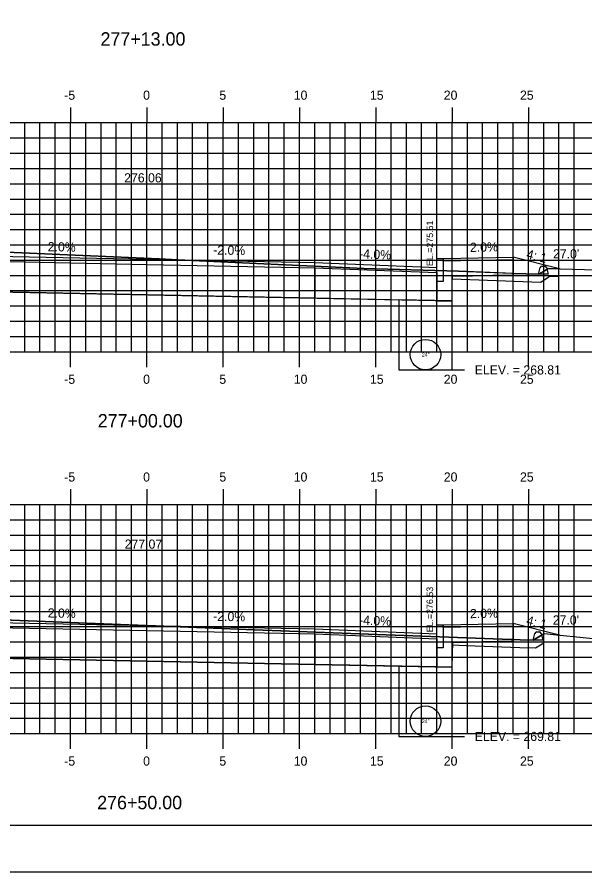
# Model space of a CAD drawing. Extents: x 854008 to 854178, y 366268 to 366378.
# Drawn here: x 854082.6 to 854119.8, y 366268.2 to 366324.1 of the extents above; entities that cross this region are included whole.
import ezdxf

# ---------------------------------------------------------------- set-up
doc = ezdxf.new("R2010")
doc.units = 0
for name, color, linetype in [('ANNOTATION', 7, 'Continuous'), ('BORDER', 7, 'Continuous'), ('D_Curb_Type_1_Rt', 7, 'Continuous'), ('D_Roadway_Centerline_Text', 7, 'Continuous'), ('D_Roadway_Edge_TW', 7, 'Continuous'), ('D_Roadway_FinishedGrade', 7, 'Continuous'), ('D_Roadway_Sidewalks_Paved', 7, 'Continuous'), ('D_Roadway_SubGrade', 7, 'Continuous'), ('D_Text_Standard', 7, 'Continuous'), ('H_V ANNOTATION', 7, 'Continuous'), ('JUNK COM EXC', 7, 'Continuous'), ('JUNK FILL', 7, 'Continuous'), ('junk grubnfill', 7, 'Continuous'), ('junk strct exc', 7, 'Continuous'), ('MAJOR', 7, 'Continuous'), ('MINOR', 7, 'Continuous'), ('PDRAIN', 7, 'Continuous'), ('PLOT BOUNDARY', 7, 'Continuous'), ('S_Curb_Type_3', 7, 'Continuous'), ('S_Roadway_Centerline', 7, 'Continuous')]:
    doc.layers.add(name, color=color, linetype=linetype)

msp = doc.modelspace()

# ---------------------------------------------------------------- linework, layer by layer
at = {"layer": 'BORDER'}
msp.add_line((854016.103, 366271.236), (854176.103, 366271.236), dxfattribs=at)
at = {"layer": 'D_Curb_Type_1_Rt'}
for points in [[(854110.52, 366308.335), (854110.52, 366306.835), (854110.103, 366306.835), (854110.103, 366308.335)], [(854110.52, 366284.352), (854110.52, 366282.852), (854110.103, 366282.852), (854110.103, 366284.352)]]:
    msp.add_lwpolyline(points, close=True, dxfattribs=at)
at = {"layer": 'D_Roadway_Edge_TW'}
for points in [[(854072.103, 366308.192), (854080.103, 366308.512), (854102.103, 366308.072), (854110.099, 366307.751)], [(854072.103, 366308.192), (854080.103, 366308.512), (854102.103, 366308.072), (854110.099, 366307.751)], [(854072.103, 366284.209), (854080.103, 366284.529), (854102.103, 366284.089), (854110.099, 366283.769)]]:
    msp.add_lwpolyline(points, dxfattribs=at)
at = {"layer": 'D_Roadway_FinishedGrade'}
for p, q in [((854118.135, 366307.67), (854115.108, 366308.426)), ((854118.135, 366283.688), (854115.108, 366284.444))]:
    msp.add_line(p, q, dxfattribs=at)
at = {"layer": 'D_Roadway_Sidewalks_Paved'}
for points in [[(854110.519, 366308.335), (854115.108, 366308.426), (854115.108, 366308.26), (854110.519, 366308.168)], [(854110.519, 366284.352), (854115.108, 366284.444), (854115.108, 366284.277), (854110.519, 366284.185)]]:
    msp.add_lwpolyline(points, close=True, dxfattribs=at)
at = {"layer": 'D_Roadway_SubGrade'}
for p, q in [((854118.103, 366307.167), (854118.103, 366307.667)), ((854117.103, 366283.18), (854117.103, 366283.77))]:
    msp.add_line(p, q, dxfattribs=at)
for points in [[(854080.103, 366306.178), (854080.103, 366308.178), (854091.103, 366307.958), (854102.103, 366307.738), (854102.103, 366305.738), (854091.103, 366305.958)], [(854102.103, 366307.738), (854110.103, 366307.418), (854110.103, 366305.578), (854102.103, 366305.738)], [(854080.103, 366282.195), (854080.103, 366284.195), (854091.103, 366283.975), (854102.103, 366283.755), (854102.103, 366281.755), (854091.103, 366281.975)], [(854102.103, 366283.755), (854110.103, 366283.435), (854110.103, 366281.595), (854102.103, 366281.755)]]:
    msp.add_lwpolyline(points, close=True, dxfattribs=at)
for points in [[(854110.106, 366305.579), (854111.106, 366305.559), (854111.106, 366307.181), (854115.108, 366307.26), (854115.108, 366308.26)], [(854111.106, 366307.019), (854116.906, 366306.801), (854117.404, 366307.112), (854117.525, 366307.182), (854118.103, 366307.167)], [(854110.106, 366281.596), (854111.106, 366281.576), (854111.106, 366283.198), (854115.108, 366283.277), (854115.108, 366284.277)], [(854111.106, 366283.037), (854112.026, 366283.002), (854114.951, 366282.895), (854115.537, 366282.874), (854116.558, 366282.839), (854117.103, 366283.18)]]:
    msp.add_lwpolyline(points, dxfattribs=at)
at = {"layer": 'D_Text_Standard'}
for points in [[(854110.987, 366301.046), (854111.226, 366301.046), (854111.906, 366301.046)], [(854110.987, 366277.046), (854111.226, 366277.046), (854111.906, 366277.046)]]:
    msp.add_lwpolyline(points, dxfattribs=at)
at = {"layer": 'JUNK COM EXC'}
for points in [[(854115.108, 366307.369), (854111.511, 366307.504), (854105.338, 366307.696), (854093.132, 366308.264), (854091.919, 366308.317), (854082.419, 366308.728), (854081.643, 366308.761), (854073.044, 366308.446), (854067.098, 366308.296), (854067.098, 366307.7), (854071.103, 366307.62), (854071.103, 366305.998), (854080.103, 366306.178), (854111.106, 366305.559), (854111.106, 366307.181), (854115.108, 366307.26), (854115.108, 366307.369)], [(854067.098, 366284.408), (854067.098, 366283.717), (854071.103, 366283.637), (854071.103, 366282.015), (854080.103, 366282.195), (854102.103, 366281.755), (854111.106, 366281.576), (854111.139, 366283.231), (854115.108, 366283.277), (854115.108, 366283.389), (854114.969, 366283.394), (854112.044, 366283.502), (854105.033, 366283.764), (854098.156, 366284.024), (854091.667, 366284.28), (854089.919, 366284.352), (854081.695, 366284.68), (854074.422, 366284.545), (854067.098, 366284.408)]]:
    msp.add_lwpolyline(points, dxfattribs=at)
at = {"layer": 'JUNK FILL'}
for points in [[(854115.103, 366307.37), (854116.772, 366307.307), (854117.147, 366307.541), (854117.398, 366307.685), (854118.135, 366307.67), (854115.108, 366308.426), (854115.103, 366308.426)], [(854115.103, 366284.444), (854115.103, 366283.39), (854115.555, 366283.373), (854116.422, 366283.344), (854117.147, 366283.798), (854118.135, 366283.688), (854115.108, 366284.444)]]:
    msp.add_lwpolyline(points, close=True, dxfattribs=at)
at = {"layer": 'junk grubnfill'}
for points in [[(854118.103, 366307.167), (854118.103, 366307.667), (854117.398, 366307.685), (854117.147, 366307.541), (854116.772, 366307.307), (854115.108, 366307.369), (854115.108, 366307.26), (854111.106, 366307.181), (854111.106, 366307.019), (854116.906, 366306.801), (854117.404, 366307.112), (854117.525, 366307.182), (854118.103, 366307.167)], [(854117.103, 366283.18), (854117.103, 366283.77), (854116.422, 366283.344), (854115.555, 366283.373), (854115.108, 366283.389), (854115.108, 366283.277), (854111.106, 366283.198), (854111.106, 366283.037), (854112.026, 366283.002), (854114.951, 366282.895), (854115.537, 366282.874), (854116.558, 366282.839), (854117.103, 366283.18)]]:
    msp.add_lwpolyline(points, dxfattribs=at)
at = {"layer": 'junk strct exc'}
for points in [[(854107.606, 366305.628), (854107.606, 366301.046), (854111.106, 366301.046), (854111.106, 366305.559)], [(854107.606, 366281.645), (854107.606, 366277.046), (854111.106, 366277.046), (854111.106, 366281.576)]]:
    msp.add_lwpolyline(points, close=True, dxfattribs=at)
at = {"layer": 'MAJOR'}
for p, q in [((854086.103, 366318.238), (854086.103, 366317.236)), ((854091.103, 366318.238), (854091.103, 366317.236)), ((854096.103, 366318.238), (854096.103, 366317.236)), ((854101.103, 366318.238), (854101.103, 366317.236)), ((854106.103, 366318.238), (854106.103, 366317.236)), ((854111.103, 366318.238), (854111.103, 366317.236)), ((854116.103, 366318.238), (854116.103, 366317.236)), ((854021.103, 366317.236), (854161.103, 366317.236)), ((854021.103, 366317.236), (854161.103, 366317.236)), ((854086.103, 366302.236), (854086.103, 366317.236)), ((854091.103, 366302.236), (854091.103, 366317.236)), ((854096.103, 366302.236), (854096.103, 366317.236)), ((854101.103, 366302.236), (854101.103, 366317.236)), ((854106.103, 366302.236), (854106.103, 366317.236)), ((854111.103, 366302.236), (854111.103, 366317.236)), ((854116.103, 366302.236), (854116.103, 366317.236)), ((854021.103, 366312.236), (854161.103, 366312.236)), ((854021.103, 366307.236), (854161.103, 366307.236)), ((854021.103, 366302.236), (854161.103, 366302.236)), ((854021.103, 366302.236), (854161.103, 366302.236)), ((854086.103, 366301.234), (854086.103, 366302.236)), ((854091.103, 366301.234), (854091.103, 366302.236)), ((854096.103, 366301.234), (854096.103, 366302.236)), ((854101.103, 366301.234), (854101.103, 366302.236)), ((854106.103, 366301.234), (854106.103, 366302.236)), ((854111.103, 366301.234), (854111.103, 366302.236)), ((854116.103, 366301.234), (854116.103, 366302.236)), ((854086.103, 366293.238), (854086.103, 366292.236)), ((854091.103, 366293.238), (854091.103, 366292.236)), ((854096.103, 366293.238), (854096.103, 366292.236)), ((854101.103, 366293.238), (854101.103, 366292.236)), ((854106.103, 366293.238), (854106.103, 366292.236)), ((854111.103, 366293.238), (854111.103, 366292.236)), ((854116.103, 366293.238), (854116.103, 366292.236)), ((854021.103, 366292.236), (854161.103, 366292.236)), ((854021.103, 366292.236), (854161.103, 366292.236)), ((854086.103, 366277.236), (854086.103, 366292.236)), ((854091.103, 366277.236), (854091.103, 366292.236)), ((854096.103, 366277.236), (854096.103, 366292.236)), ((854101.103, 366277.236), (854101.103, 366292.236)), ((854106.103, 366277.236), (854106.103, 366292.236)), ((854111.103, 366277.236), (854111.103, 366292.236)), ((854116.103, 366277.236), (854116.103, 366292.236)), ((854021.103, 366287.236), (854161.103, 366287.236)), ((854021.103, 366282.236), (854161.103, 366282.236)), ((854021.103, 366277.236), (854161.103, 366277.236)), ((854021.103, 366277.236), (854161.103, 366277.236)), ((854086.103, 366276.234), (854086.103, 366277.236)), ((854091.103, 366276.234), (854091.103, 366277.236)), ((854096.103, 366276.234), (854096.103, 366277.236)), ((854101.103, 366276.234), (854101.103, 366277.236)), ((854106.103, 366276.234), (854106.103, 366277.236)), ((854111.103, 366276.234), (854111.103, 366277.236)), ((854116.103, 366276.234), (854116.103, 366277.236))]:
    msp.add_line(p, q, dxfattribs=at)
at = {"layer": 'MINOR'}
for p, q in [((854083.103, 366302.236), (854083.103, 366317.236)), ((854084.103, 366302.236), (854084.103, 366317.236)), ((854085.103, 366302.236), (854085.103, 366317.236)), ((854087.103, 366302.236), (854087.103, 366317.236)), ((854088.103, 366302.236), (854088.103, 366317.236)), ((854089.103, 366302.236), (854089.103, 366317.236)), ((854090.103, 366302.236), (854090.103, 366317.236)), ((854092.103, 366302.236), (854092.103, 366317.236)), ((854093.103, 366302.236), (854093.103, 366317.236)), ((854094.103, 366302.236), (854094.103, 366317.236)), ((854095.103, 366302.236), (854095.103, 366317.236)), ((854097.103, 366302.236), (854097.103, 366317.236)), ((854098.103, 366302.236), (854098.103, 366317.236)), ((854099.103, 366302.236), (854099.103, 366317.236)), ((854100.103, 366302.236), (854100.103, 366317.236)), ((854102.103, 366302.236), (854102.103, 366317.236)), ((854103.103, 366302.236), (854103.103, 366317.236)), ((854104.103, 366302.236), (854104.103, 366317.236)), ((854105.103, 366302.236), (854105.103, 366317.236)), ((854107.103, 366302.236), (854107.103, 366317.236)), ((854108.103, 366302.236), (854108.103, 366317.236)), ((854109.103, 366302.236), (854109.103, 366317.236)), ((854110.103, 366302.236), (854110.103, 366317.236)), ((854112.103, 366302.236), (854112.103, 366317.236)), ((854113.103, 366302.236), (854113.103, 366317.236)), ((854114.103, 366302.236), (854114.103, 366317.236)), ((854115.103, 366302.236), (854115.103, 366317.236)), ((854117.103, 366302.236), (854117.103, 366317.236)), ((854118.103, 366302.236), (854118.103, 366317.236)), ((854119.103, 366302.236), (854119.103, 366317.236)), ((854021.103, 366316.236), (854161.103, 366316.236)), ((854021.103, 366315.236), (854161.103, 366315.236)), ((854021.103, 366314.236), (854161.103, 366314.236)), ((854021.103, 366313.236), (854161.103, 366313.236)), ((854021.103, 366311.236), (854161.103, 366311.236)), ((854021.103, 366310.236), (854161.103, 366310.236)), ((854021.103, 366309.236), (854161.103, 366309.236)), ((854021.103, 366308.236), (854161.103, 366308.236)), ((854021.103, 366306.236), (854161.103, 366306.236)), ((854021.103, 366305.236), (854161.103, 366305.236)), ((854021.103, 366304.236), (854161.103, 366304.236)), ((854021.103, 366303.236), (854161.103, 366303.236)), ((854083.103, 366277.236), (854083.103, 366292.236)), ((854084.103, 366277.236), (854084.103, 366292.236)), ((854085.103, 366277.236), (854085.103, 366292.236)), ((854087.103, 366277.236), (854087.103, 366292.236)), ((854088.103, 366277.236), (854088.103, 366292.236)), ((854089.103, 366277.236), (854089.103, 366292.236)), ((854090.103, 366277.236), (854090.103, 366292.236)), ((854092.103, 366277.236), (854092.103, 366292.236)), ((854093.103, 366277.236), (854093.103, 366292.236)), ((854094.103, 366277.236), (854094.103, 366292.236)), ((854095.103, 366277.236), (854095.103, 366292.236)), ((854097.103, 366277.236), (854097.103, 366292.236)), ((854098.103, 366277.236), (854098.103, 366292.236)), ((854099.103, 366277.236), (854099.103, 366292.236)), ((854100.103, 366277.236), (854100.103, 366292.236)), ((854102.103, 366277.236), (854102.103, 366292.236)), ((854103.103, 366277.236), (854103.103, 366292.236)), ((854104.103, 366277.236), (854104.103, 366292.236)), ((854105.103, 366277.236), (854105.103, 366292.236)), ((854107.103, 366277.236), (854107.103, 366292.236)), ((854108.103, 366277.236), (854108.103, 366292.236)), ((854109.103, 366277.236), (854109.103, 366292.236)), ((854110.103, 366277.236), (854110.103, 366292.236)), ((854112.103, 366277.236), (854112.103, 366292.236)), ((854113.103, 366277.236), (854113.103, 366292.236)), ((854114.103, 366277.236), (854114.103, 366292.236)), ((854115.103, 366277.236), (854115.103, 366292.236)), ((854117.103, 366277.236), (854117.103, 366292.236)), ((854118.103, 366277.236), (854118.103, 366292.236)), ((854119.103, 366277.236), (854119.103, 366292.236)), ((854021.103, 366291.236), (854161.103, 366291.236)), ((854021.103, 366290.236), (854161.103, 366290.236)), ((854021.103, 366289.236), (854161.103, 366289.236)), ((854021.103, 366288.236), (854161.103, 366288.236)), ((854021.103, 366286.236), (854161.103, 366286.236)), ((854021.103, 366285.236), (854161.103, 366285.236)), ((854021.103, 366284.236), (854161.103, 366284.236)), ((854021.103, 366283.236), (854161.103, 366283.236)), ((854021.103, 366281.236), (854161.103, 366281.236)), ((854021.103, 366280.236), (854161.103, 366280.236)), ((854021.103, 366279.236), (854161.103, 366279.236)), ((854021.103, 366278.236), (854161.103, 366278.236))]:
    msp.add_line(p, q, dxfattribs=at)
at = {"layer": 'PDRAIN'}
for points in [[(854107.606, 366305.628), (854107.606, 366301.046), (854111.106, 366301.046), (854111.106, 366305.559)], [(854107.606, 366281.645), (854107.606, 366277.046), (854111.106, 366277.046), (854111.106, 366281.576)]]:
    msp.add_lwpolyline(points, dxfattribs=at)
for centre in [(854109.356, 366302.046), (854109.356, 366278.046)]:
    msp.add_circle(centre, 1, dxfattribs=at)
at = {"layer": 'PLOT BOUNDARY'}
msp.add_lwpolyline([(854008.01, 366268.177), (854178.01, 366268.177), (854178.01, 366378.177), (854008.01, 366378.177)], close=True, dxfattribs=at)
at = {"layer": 'S_Curb_Type_3'}
for points in [[(854116.996, 366307.849), (854117.172, 366307.849)], [(854117.294, 366307.752), (854117.397, 366307.307), (854116.772, 366307.307), (854116.874, 366307.752)], [(854116.944, 366283.789), (854117.047, 366283.344), (854116.422, 366283.344), (854116.525, 366283.789)], [(854116.647, 366283.886), (854116.823, 366283.886)]]:
    msp.add_lwpolyline(points, dxfattribs=at)
for centre, start, end in [((854116.996, 366307.724), 90, 167.0054), ((854117.172, 366307.724), 12.9946, 90), ((854116.647, 366283.761), 90, 167.0054), ((854116.823, 366283.761), 12.9946, 90)]:
    msp.add_arc(centre, 0.125, start, end, dxfattribs=at)
at = {"layer": 'S_Roadway_Centerline'}
for points in [[(854045.227, 366308.341), (854048.296, 366308.548), (854053.398, 366308.978), (854055.631, 366309.052), (854057.135, 366309.068), (854058.916, 366309.105), (854059.325, 366309.117), (854060.2, 366308.968), (854062.29, 366308.522), (854062.513, 366308.469), (854062.691, 366308.316), (854063.611, 366308.208), (854073.044, 366308.446), (854081.643, 366308.761), (854082.419, 366308.728), (854091.919, 366308.317), (854093.132, 366308.264), (854105.338, 366307.696), (854111.511, 366307.504), (854116.772, 366307.307), (854117.147, 366307.541), (854117.398, 366307.685), (854122.963, 366307.541)], [(854042.191, 366285.155), (854046.454, 366284.186), (854046.938, 366284.068), (854050.758, 366284.093), (854057.251, 366284.194), (854058.422, 366284.245), (854074.422, 366284.545), (854081.695, 366284.68), (854089.919, 366284.352), (854091.667, 366284.28), (854098.156, 366284.024), (854105.033, 366283.764), (854112.044, 366283.502), (854114.969, 366283.394), (854115.555, 366283.373), (854116.422, 366283.344), (854117.122, 366283.782), (854117.147, 366283.798), (854117.542, 366283.751), (854119.24, 366283.569), (854127.488, 366282.734)]]:
    msp.add_lwpolyline(points, dxfattribs=at)

# ---------------------------------------------------------------- texts
at = {"layer": 'ANNOTATION'}
for s, rotation, p in [('2.0%', 358.8542, (854084.607, 366308.822)), ('-2.0%', 358.8542, (854095.446, 366308.605)), ('2.0%', 1.138, (854112.278, 366308.771)), ('-4.0%', 357.7095, (854104.999, 366308.356)), ('4: 1', 345.9638, (854115.926, 366308.365)), ('2.0%', 358.8542, (854084.607, 366284.839)), ('-2.0%', 358.8542, (854095.446, 366284.622)), ('-4.0%', 357.7093, (854104.997, 366284.374)), ('2.0%', 1.148, (854112.278, 366284.788)), ('4: 1', 345.9638, (854115.925, 366284.383))]:
    msp.add_text(s, height=0.6, rotation=rotation, dxfattribs=at).set_placement(p)
at = {"layer": 'D_Roadway_Centerline_Text'}
for s, p in [('276.06', (854089.621, 366313.324)), ('277.07', (854089.653, 366289.341))]:
    msp.add_text(s, height=0.6, dxfattribs=at).set_placement(p)
at = {"layer": 'D_Text_Standard'}
for s, p in [(' EL.=275.51', (854109.858, 366307.683)), (' EL.=276.53', (854109.858, 366283.7))]:
    msp.add_text(s, height=0.4335, rotation=90, dxfattribs=at).set_placement(p)
for s, p in [("27.0'", (854117.712, 366308.346)), ('ELEV. = 268.81', (854112.585, 366300.746)), ("27.0'", (854117.699, 366284.372)), ('ELEV. = 269.81', (854112.586, 366276.746))]:
    msp.add_text(s, height=0.6, dxfattribs=at).set_placement(p)
at = {"layer": 'H_V ANNOTATION'}
for s, height, p in [('277+13.00', 0.875, (854088.068, 366322.28)), ('-5', 0.6, (854085.694, 366318.736)), ('0', 0.6, (854090.862, 366318.736)), ('5', 0.6, (854095.854, 366318.736)), ('10', 0.6, (854100.728, 366318.736)), ('15', 0.6, (854105.72, 366318.736)), ('20', 0.6, (854110.557, 366318.736)), ('25', 0.6, (854115.549, 366318.736)), ('-5', 0.6, (854085.694, 366300.136)), ('0', 0.6, (854090.862, 366300.136)), ('5', 0.6, (854095.854, 366300.136)), ('10', 0.6, (854100.728, 366300.136)), ('15', 0.6, (854105.72, 366300.136)), ('20', 0.6, (854110.557, 366300.136)), ('25', 0.6, (854115.549, 366300.136)), ('277+00.00', 0.875, (854087.888, 366297.28)), ('-5', 0.6, (854085.694, 366293.736)), ('0', 0.6, (854090.862, 366293.736)), ('5', 0.6, (854095.854, 366293.736)), ('10', 0.6, (854100.728, 366293.736)), ('15', 0.6, (854105.72, 366293.736)), ('20', 0.6, (854110.557, 366293.736)), ('25', 0.6, (854115.549, 366293.736)), ('-5', 0.6, (854085.694, 366275.136)), ('0', 0.6, (854090.862, 366275.136)), ('5', 0.6, (854095.854, 366275.136)), ('10', 0.6, (854100.728, 366275.136)), ('15', 0.6, (854105.72, 366275.136)), ('20', 0.6, (854110.557, 366275.136)), ('25', 0.6, (854115.549, 366275.136)), ('276+50.00', 0.875, (854087.849, 366272.28))]:
    msp.add_text(s, height=height, dxfattribs=at).set_placement(p)
at = {"layer": 'PDRAIN'}
for p in [(854109.114, 366301.921), (854109.114, 366277.921)]:
    msp.add_text('24"', height=0.25, dxfattribs=at).set_placement(p)
at = {"layer": 'S_Roadway_Centerline'}
for s, p in [('C', (854091.913, 366308.317)), ('L', (854091.919, 366308.31)), ('C', (854091.662, 366284.28)), ('L', (854091.667, 366284.273))]:
    msp.add_text(s, height=0.0146, dxfattribs=at).set_placement(p)

doc.saveas('drawing.dxf')
